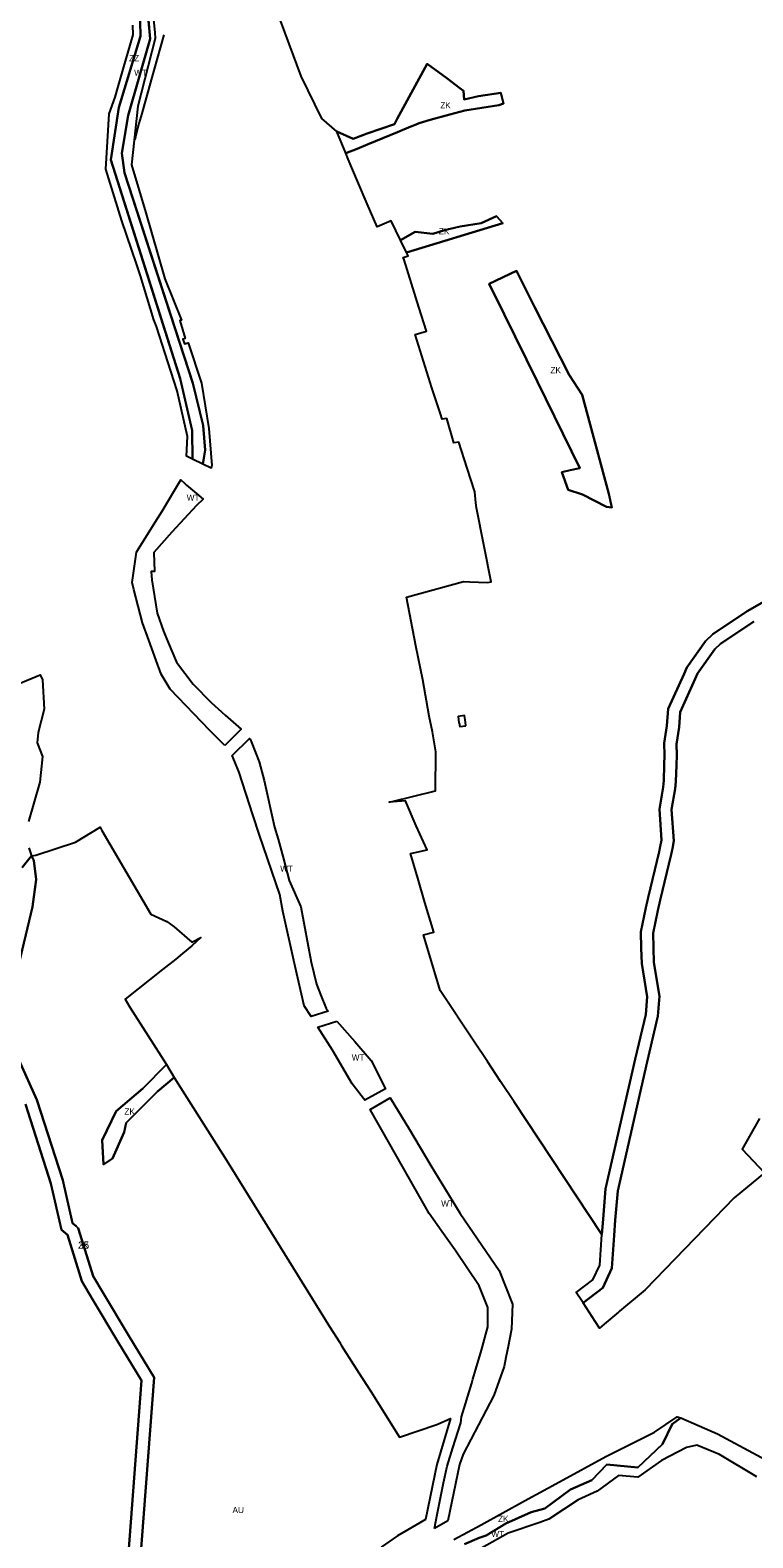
# Model space of a CAD drawing. Extents: x -521261 to -517465, y -1182764 to -1179456.
# Drawn here: x -519568 to -518978, y -1182068 to -1180835 of the extents above; entities that cross this region are included whole.
import ezdxf

# ---------------------------------------------------------------- set-up
doc = ezdxf.new("R2010")
doc.units = 0
for name, color, linetype in [('90640013', 7, 'Continuous'), ('90670013', 7, 'Continuous'), ('90710013', 7, 'Continuous'), ('90710023', 7, 'Continuous'), ('90750013', 7, 'Continuous'), ('90910012', 7, 'Continuous'), ('ID_navrh', 7, 'Continuous')]:
    doc.layers.add(name, color=color, linetype=linetype)

msp = doc.modelspace()

# ---------------------------------------------------------------- linework, layer by layer
at = {"layer": '90640013'}
for points in [[(-519473.15, -1180811.61), (-519470.44, -1180842.25), (-519488.4, -1180904.99), (-519493.48, -1180935.68), (-519491.42, -1180951.86), (-519435.57, -1181123.54), (-519427.15, -1181158.29), (-519425.48, -1181178.36), (-519427.239, -1181189.828), (-519435.742, -1181185.683), (-519435.91, -1181162.44), (-519445.77, -1181119.72), (-519502.58, -1180941.01), (-519495.82, -1180898.23), (-519478.12, -1180840), (-519478.91, -1180815.91)], [(-519213.54, -1182072.66), (-519201.77, -1182067.5), (-519195.94, -1182065.5), (-519179.95, -1182055.88), (-519159.13, -1182046.65), (-519148.1, -1182043.62), (-519126.93, -1182028.03), (-519109.68, -1182020.3), (-519097.34, -1182007.47), (-519072.08, -1182009.92), (-519051.9, -1181990.97), (-519043.95, -1181974.52), (-519037.03, -1181969.53), (-519007.07, -1181982.5), (-518967.52, -1182003.69)], [(-518974.73, -1182017.76), (-519005.47, -1181999.42), (-519023.89, -1181991.86), (-519032.35, -1181993.68), (-519052.86, -1182004.21), (-519071.99, -1182018.05), (-519087.95, -1182016.65), (-519105.37, -1182029.49), (-519120.85, -1182036.4), (-519144.87, -1182052.15), (-519152.16, -1182054.92), (-519178.02, -1182063.84), (-519208.47, -1182080.89)]]:
    msp.add_lwpolyline(points, dxfattribs=at)
for points in [[(-519409.389, -1181419.917), (-519412.61, -1181416.64), (-519421.56, -1181407.62), (-519454.05, -1181373.8), (-519461.32, -1181361.65), (-519465.42, -1181350.42), (-519471.53, -1181333.7), (-519476.71, -1181319.53), (-519483.7, -1181292.46), (-519485.03, -1181286.53), (-519481.6, -1181261.79), (-519479.97, -1181259.11), (-519464.29, -1181234.25), (-519460.68, -1181228.41), (-519450.28, -1181210.83), (-519445.38, -1181202.73), (-519442.35, -1181205.48), (-519440.69, -1181206.91), (-519432.6, -1181213.97), (-519427.07, -1181218.6), (-519432.4, -1181223.78), (-519452.53, -1181245.44), (-519467.41, -1181262.05), (-519466.74, -1181277.55), (-519469.58, -1181277.72), (-519469.05, -1181284.33), (-519464.71, -1181311.78), (-519459.51, -1181326.26), (-519455.66, -1181335.73), (-519448.71, -1181351.86), (-519435.17, -1181369.79), (-519420.51, -1181384.61), (-519409.19, -1181394.99), (-519395.935, -1181406.485)], [(-519324.89, -1181637.01), (-519324.89, -1181637.01), (-519338.936, -1181641.334), (-519344.46, -1181632.66), (-519351.95, -1181600.47), (-519362.01, -1181555.36), (-519364.56, -1181541.56), (-519380.95, -1181493.03), (-519386.52, -1181476.56), (-519397.54, -1181441.8), (-519401.11, -1181433.16), (-519403.401, -1181428.069), (-519389.322, -1181414.013), (-519388.77, -1181414.67), (-519387.43, -1181418.03), (-519381.19, -1181433.32), (-519377.23, -1181448.55), (-519368.74, -1181486.67), (-519365.68, -1181496.5), (-519361.63, -1181511.27), (-519356.79, -1181530.1), (-519347.34, -1181551.68), (-519338.86, -1181596.87), (-519334.56, -1181614.89), (-519331.36, -1181623.53), (-519326.59, -1181634.95)], [(-519317.776, -1181645.284), (-519303.16, -1181661.78), (-519289.97, -1181677.24), (-519278.04, -1181700.51), (-519295.09, -1181709.75), (-519296.21, -1181708.36), (-519298.01, -1181706.05), (-519305.33, -1181696.42), (-519321.38, -1181668.9), (-519333.365, -1181650.082)], [(-519238.255, -1182059.95), (-519235.92, -1182048.33), (-519230.66, -1182022.59), (-519227.85, -1182009.01), (-519223.16, -1181994.1), (-519216.64, -1181973.55), (-519215.94, -1181968.54), (-519207.75, -1181941.19), (-519206.76, -1181937.89), (-519205.11, -1181932.39), (-519199.86, -1181914.01), (-519194.44, -1181895.04), (-519194.53, -1181879.24), (-519201.77, -1181861.67), (-519221.32, -1181832.36), (-519230.68, -1181818.97), (-519242.36, -1181802.29), (-519281.3, -1181733.63), (-519286.8, -1181724.28), (-519290.763, -1181717.333), (-519274.23, -1181707.9), (-519258.46, -1181733.82), (-519241.25, -1181763.27), (-519217.16, -1181802.34), (-519185.2, -1181849.05), (-519174.51, -1181876.42), (-519175.37, -1181897.02), (-519178.25, -1181912.58), (-519178.69, -1181914.95), (-519179.74, -1181920.09), (-519181.25, -1181927.45), (-519189.77, -1181951.14), (-519214.66, -1181999.21), (-519217.66, -1182007.47), (-519227.185, -1182053.534)]]:
    msp.add_lwpolyline(points, close=True, dxfattribs=at)
at = {"layer": '90670013'}
for points in [[(-519469.058, -1180813.289), (-519466.67, -1180837.06), (-519466.18, -1180841.84), (-519480.35, -1180897.31), (-519485.52, -1180945.19), (-519473.83, -1180984.46), (-519464.097, -1181018.489), (-519458.43, -1181038.3), (-519444.83, -1181072.14), (-519445.99, -1181072.34), (-519441.75, -1181087.15), (-519443.6, -1181087.68), (-519442.29, -1181091.61), (-519439.26, -1181090.75), (-519428.49, -1181123.78), (-519422.52, -1181160.74), (-519419.92, -1181190.94), (-519420.397, -1181193.163), (-519427.239, -1181189.828), (-519425.48, -1181178.36), (-519427.15, -1181158.29), (-519435.57, -1181123.54), (-519469.036, -1181020.668), (-519491.42, -1180951.86), (-519493.48, -1180935.68), (-519488.4, -1180904.99), (-519470.44, -1180842.25), (-519473.044, -1180812.806)], [(-519478.91, -1180815.91), (-519478.12, -1180840), (-519495.82, -1180898.23), (-519502.58, -1180941.01), (-519476.374, -1181023.446), (-519445.77, -1181119.72), (-519435.91, -1181162.44), (-519435.742, -1181185.683), (-519440.793, -1181183.221), (-519439.93, -1181167.27), (-519448.2, -1181129.83), (-519458.37, -1181098.48), (-519460.28, -1181092.58), (-519465.27, -1181077.26), (-519466.73, -1181073.28), (-519467.25, -1181071.87), (-519478.17, -1181035.82), (-519481.61, -1181026.09), (-519493.55, -1180991.1), (-519506.51, -1180948.83), (-519503.72, -1180903.54), (-519498.93, -1180889.82), (-519492.45, -1180866.93), (-519484.35, -1180839.02), (-519484.62, -1180831.05)]]:
    msp.add_lwpolyline(points, dxfattribs=at)
at = {"layer": '90710013'}
for points in [[(-519268.52, -1180907.46), (-519253.98, -1180880.7), (-519244.16, -1180862.53), (-519228.167, -1180874.44), (-519217.362, -1180882.487), (-519214.35, -1180884.73), (-519213.96, -1180891.71), (-519202.16, -1180889.15), (-519184.03, -1180886.23), (-519181.69, -1180894.95), (-519185.49, -1180896.3), (-519213.45, -1180900.71), (-519225.65, -1180904.08), (-519241.56, -1180908.49), (-519250.72, -1180911.24), (-519254.39, -1180912.8), (-519257.44, -1180913.87), (-519268.27, -1180918.36), (-519292.23, -1180928.39), (-519301.18, -1180932.18), (-519310.648, -1180935.544), (-519317.97, -1180917.99), (-519304.48, -1180923.88), (-519293.06, -1180919.67), (-519270.91, -1180912.06)], [(-519239.59, -1181001.51), (-519230.03, -1180998.72), (-519217.21, -1180995.57), (-519199.91, -1180992.98), (-519187.6, -1180987.07), (-519182.22, -1180992.98), (-519261.07, -1181016.81), (-519265.89, -1181006.88), (-519253.85, -1181000.02)], [(-519095.79, -1181214.24), (-519093.4, -1181225.17), (-519097.52, -1181224.74), (-519117.3, -1181214.66), (-519128.84, -1181210.98), (-519134.006, -1181196.371), (-519127.28, -1181194.73), (-519119.41, -1181193.2), (-519154.06, -1181122.61), (-519181.18, -1181067.29), (-519193.42, -1181042.39), (-519171.09, -1181031.72), (-519156.38, -1181061.23), (-519128.11, -1181116.88), (-519117.61, -1181133.12), (-519111.04, -1181157.52)], [(-519491.57, -1181735.94), (-519501.06, -1181757.42), (-519508.54, -1181762.3), (-519509.68, -1181742.43), (-519498.2, -1181718.82), (-519476.47, -1181700.33), (-519457.1, -1181680.7), (-519450.65, -1181691.27), (-519464.34, -1181702.69), (-519489.97, -1181728.17)]]:
    msp.add_lwpolyline(points, close=True, dxfattribs=at)
msp.add_lwpolyline([(-519222.3, -1182068.89), (-519199.92, -1182056.85), (-519164.56, -1182037.39), (-519135.97, -1182021.78), (-519098.32, -1182001.18), (-519058.43, -1181981.09), (-519040, -1181968.57), (-519037.03, -1181969.53), (-519043.95, -1181974.52), (-519051.9, -1181990.97), (-519072.08, -1182009.92), (-519097.34, -1182007.47), (-519109.68, -1182020.3), (-519126.93, -1182028.03), (-519148.1, -1182043.62), (-519159.13, -1182046.65), (-519179.95, -1182055.88), (-519195.94, -1182065.5), (-519201.77, -1182067.5), (-519213.54, -1182072.66)], dxfattribs=at)
at = {"layer": '90710023'}
for points in [[(-518977.383, -1181318.492), (-519004.519, -1181336.714), (-519009.203, -1181341.219), (-519023.249, -1181361.087), (-519025.201, -1181365.417), (-519037.519, -1181392.468), (-519038.432, -1181404.848), (-519040.407, -1181418.631), (-519040.238, -1181427.77), (-519040.424, -1181436.046), (-519040.96, -1181449.219), (-519041.573, -1181455.371), (-519044.435, -1181472.293), (-519042.763, -1181497.712), (-519043.876, -1181504.139), (-519044.799, -1181508.83), (-519053.852, -1181546.315), (-519055.755, -1181554.74), (-519059.551, -1181573.17), (-519059.214, -1181585.154), (-519058.91, -1181597.25), (-519054.496, -1181624.81), (-519055.598, -1181641.135), (-519064.409, -1181678.49), (-519088.456, -1181783.836), (-519090.501, -1181807.769), (-519091.421, -1181820.385), (-519093.367, -1181847.085), (-519100.708, -1181863.197), (-519116.836, -1181875.406), (-519117.928, -1181873.724), (-519122.3, -1181867), (-519108.76, -1181856.75), (-519103.21, -1181844.57), (-519101.394, -1181819.658), (-519100.47, -1181806.98), (-519098.36, -1181782.29), (-519074.15, -1181676.23), (-519065.52, -1181639.64), (-519064.55, -1181625.27), (-519068.89, -1181598.17), (-519069.21, -1181585.42), (-519069.58, -1181572.29), (-519065.53, -1181552.63), (-519063.59, -1181544.04), (-519054.57, -1181506.69), (-519053.71, -1181502.32), (-519052.82, -1181497.18), (-519054.49, -1181471.78), (-519051.49, -1181454.04), (-519050.94, -1181448.52), (-519050.42, -1181435.73), (-519050.24, -1181427.75), (-519050.42, -1181418.01), (-519048.38, -1181403.77), (-519047.36, -1181389.95), (-519034.31, -1181361.29), (-519031.97, -1181356.1), (-519016.82, -1181334.67), (-519010.82, -1181328.9), (-518982.66, -1181309.99), (-518953.51, -1181293.31)], [(-519574.763, -1181519.484), (-519567.26, -1181509.91), (-519565.36, -1181513.85), (-519563.51, -1181529.49), (-519566.46, -1181551.62), (-519579.08, -1181604.33)], [(-519577.34, -1181677.47), (-519562.88, -1181709.42), (-519541.79, -1181775.11), (-519533.67, -1181810.31), (-519530.74, -1181812.82), (-519529.03, -1181814.46), (-519523.41, -1181832.63), (-519516.92, -1181853.55), (-519508.53, -1181867.8), (-519487.9, -1181902.3), (-519467.21, -1181936.45), (-519478.73, -1182090.66)], [(-519489.037, -1182094.401), (-519477.42, -1181938.895), (-519496.468, -1181907.457), (-519517.13, -1181872.903), (-519526.127, -1181857.622), (-519532.962, -1181835.589), (-519537.803, -1181819.937), (-519542.674, -1181815.764), (-519551.44, -1181777.767), (-519572.226, -1181713.022)]]:
    msp.add_lwpolyline(points, dxfattribs=at)
at = {"layer": '90750013'}
for points in [[(-518953.51, -1181293.31), (-518982.66, -1181309.99), (-519010.82, -1181328.9), (-519016.82, -1181334.67), (-519031.97, -1181356.1), (-519034.31, -1181361.29), (-519047.36, -1181389.95), (-519048.38, -1181403.77), (-519050.42, -1181418.01), (-519050.24, -1181427.75), (-519050.42, -1181435.73), (-519050.94, -1181448.52), (-519051.49, -1181454.04), (-519054.49, -1181471.78), (-519052.82, -1181497.18), (-519053.71, -1181502.32), (-519054.57, -1181506.69), (-519063.59, -1181544.04), (-519065.53, -1181552.63), (-519069.58, -1181572.29), (-519069.21, -1181585.42), (-519068.89, -1181598.17), (-519064.55, -1181625.27), (-519065.52, -1181639.64), (-519074.15, -1181676.23), (-519098.36, -1181782.29), (-519100.47, -1181806.98), (-519101.394, -1181819.658), (-519173.08, -1181711.239), (-519184.157, -1181694.485), (-519194.956, -1181678.152), (-519205.871, -1181661.644), (-519233.36, -1181620.07), (-519247.21, -1181574.73), (-519238.79, -1181572.54), (-519246.09, -1181548.32), (-519251.7, -1181528.29), (-519257.65, -1181508.26), (-519244.05, -1181505.15), (-519252.99, -1181485.52), (-519261.93, -1181465.17), (-519275.14, -1181466.21), (-519272.69, -1181465.63), (-519237.38, -1181456.93), (-519236.95, -1181424.9), (-519239.68, -1181408.57), (-519242.41, -1181395.97), (-519247.74, -1181366.2), (-519253.5, -1181338.25), (-519260.93, -1181298.71), (-519214.55, -1181285.79), (-519209.28, -1181285.94), (-519195.05, -1181286.72), (-519191.78, -1181286.11), (-519203.84, -1181225.47), (-519204.3, -1181221.58), (-519205.22, -1181212.45), (-519211.39, -1181193.2), (-519218.22, -1181171.9), (-519222.4, -1181172.34), (-519228.13, -1181152.65), (-519231.918, -1181153.175), (-519233.32, -1181148.86), (-519236.78, -1181138.21), (-519240.2, -1181127.43), (-519253.993, -1181083.953), (-519244.79, -1181081.1), (-519251.03, -1181061.46), (-519256.86, -1181042.2), (-519262.94, -1181022.92), (-519263.605, -1181020.81), (-519259.672, -1181019.689), (-519261.07, -1181016.81), (-519182.22, -1180992.98), (-519187.6, -1180987.07), (-519199.91, -1180992.98), (-519217.21, -1180995.57), (-519230.03, -1180998.72), (-519239.59, -1181001.51), (-519253.85, -1181000.02), (-519265.89, -1181006.88), (-519273.45, -1180991.01), (-519284.93, -1180995.85), (-519293.04, -1180977.04), (-519300.92, -1180958.54), (-519308.56, -1180940.55), (-519310.648, -1180935.544), (-519301.18, -1180932.18), (-519292.23, -1180928.39), (-519268.27, -1180918.36), (-519257.44, -1180913.87), (-519254.39, -1180912.8), (-519250.72, -1180911.24), (-519241.56, -1180908.49), (-519225.65, -1180904.08), (-519213.45, -1180900.71), (-519185.49, -1180896.3), (-519181.69, -1180894.95), (-519184.03, -1180886.23), (-519202.16, -1180889.15), (-519213.96, -1180891.71), (-519214.35, -1180884.73), (-519217.362, -1180882.487), (-519228.167, -1180874.44), (-519244.16, -1180862.53), (-519253.98, -1180880.7), (-519268.52, -1180907.46), (-519270.91, -1180912.06), (-519293.06, -1180919.67), (-519304.48, -1180923.88), (-519317.97, -1180917.99), (-519330.01, -1180907.41), (-519346.93, -1180872.84), (-519370.039, -1180810.159)], [(-518972.73, -1181724.81), (-518986.79, -1181749.85), (-518968.7, -1181769.11), (-518993.46, -1181789.66), (-519066.19, -1181864.73), (-519087.04, -1181882.36), (-519087.74, -1181882.98), (-519099.42, -1181892.97), (-519103.33, -1181896.18), (-519106.847, -1181890.769), (-519116.836, -1181875.406), (-519100.708, -1181863.197), (-519093.367, -1181847.085), (-519091.421, -1181820.385), (-519090.501, -1181807.769), (-519088.456, -1181783.836), (-519064.409, -1181678.49), (-519055.598, -1181641.135), (-519054.496, -1181624.81), (-519058.91, -1181597.25), (-519059.214, -1181585.154), (-519059.551, -1181573.17), (-519055.755, -1181554.74), (-519053.852, -1181546.315), (-519044.799, -1181508.83), (-519043.876, -1181504.139), (-519042.763, -1181497.712), (-519044.435, -1181472.293), (-519041.573, -1181455.371), (-519040.96, -1181449.219), (-519040.424, -1181436.046), (-519040.238, -1181427.77), (-519040.407, -1181418.631), (-519038.432, -1181404.848), (-519037.519, -1181392.468), (-519025.201, -1181365.417), (-519023.249, -1181361.087), (-519009.203, -1181341.219), (-519004.519, -1181336.714), (-518977.383, -1181318.492)], [(-519577.82, -1181369.5), (-519560.15, -1181361.95), (-519558.28, -1181366.15), (-519556.82, -1181390.16), (-519561.9, -1181409.19), (-519562.53, -1181417.65), (-519558.29, -1181428.74), (-519560.34, -1181449.96), (-519569.85, -1181481.93)], [(-519579.08, -1181604.33), (-519566.46, -1181551.62), (-519563.51, -1181529.49), (-519565.36, -1181513.85), (-519567.26, -1181509.91), (-519563.86, -1181509.62), (-519531.34, -1181498.84), (-519511.19, -1181486.58), (-519509.72, -1181489.33), (-519469.92, -1181557.79), (-519456.65, -1181563.71), (-519450.63, -1181567.98), (-519436.26, -1181580.5), (-519428.99, -1181576.87), (-519436.43, -1181583.74), (-519444.05, -1181589.92), (-519449.37, -1181594.38), (-519460.32, -1181602.95), (-519490.67, -1181627.18), (-519486.95, -1181633.64), (-519457.1, -1181680.7), (-519476.47, -1181700.33), (-519498.2, -1181718.82), (-519509.68, -1181742.43), (-519508.54, -1181762.3), (-519501.06, -1181757.42), (-519491.57, -1181735.94), (-519489.97, -1181728.17), (-519464.34, -1181702.69), (-519450.65, -1181691.27), (-519407.91, -1181758.76), (-519323.87, -1181894.73), (-519315.5, -1181907.95), (-519314.23, -1181910.15), (-519299.96, -1181932.54), (-519293.32, -1181942.71), (-519289.74, -1181948.32), (-519287.24, -1181952.67), (-519273.97, -1181973.58), (-519266.78, -1181985.29), (-519236.18, -1181974.91), (-519225.183, -1181970.09), (-519236.113, -1182007.614), (-519245.606, -1182052.653), (-519250.079, -1182055.246), (-519259.955, -1182060.97), (-519268.355, -1182065.839), (-519281.77, -1182075.133)], [(-519569.38, -1181503.52), (-519567.26, -1181509.91), (-519574.763, -1181519.484)], [(-519478.73, -1182090.66), (-519467.21, -1181936.45), (-519487.9, -1181902.3), (-519508.53, -1181867.8), (-519516.92, -1181853.55), (-519523.41, -1181832.63), (-519529.03, -1181814.46), (-519530.74, -1181812.82), (-519533.67, -1181810.31), (-519541.79, -1181775.11), (-519562.88, -1181709.42), (-519577.34, -1181677.47)], [(-519572.226, -1181713.022), (-519551.44, -1181777.767), (-519542.674, -1181815.764), (-519537.803, -1181819.937), (-519532.962, -1181835.589), (-519526.127, -1181857.622), (-519517.13, -1181872.903), (-519496.468, -1181907.457), (-519477.42, -1181938.895), (-519489.037, -1182094.401), (-519490.964, -1182123.644), (-519496.983, -1182156.235), (-519510.122, -1182231.787), (-519530.261, -1182347.588), (-519534.18, -1182347.06), (-519550.42, -1182341.81), (-519569.087, -1182337.379)]]:
    msp.add_lwpolyline(points, dxfattribs=at)
for points in [[(-519093.4, -1181225.17), (-519095.79, -1181214.24), (-519111.04, -1181157.52), (-519117.61, -1181133.12), (-519128.11, -1181116.88), (-519156.38, -1181061.23), (-519171.09, -1181031.72), (-519193.42, -1181042.39), (-519181.18, -1181067.29), (-519154.06, -1181122.61), (-519119.41, -1181193.2), (-519127.28, -1181194.73), (-519134.006, -1181196.371), (-519128.84, -1181210.98), (-519117.3, -1181214.66), (-519097.52, -1181224.74)], [(-519212.46, -1181403.8), (-519212.84, -1181400.66), (-519213.49, -1181395.41), (-519218.86, -1181396.18), (-519218.13, -1181401.43), (-519217.94, -1181401.4), (-519217.55, -1181404.42)]]:
    msp.add_lwpolyline(points, close=True, dxfattribs=at)
at = {"layer": '90910012'}
for points in [[(-519462.25, -1180849.48), (-519469.64, -1180875.84)], [(-519459.09, -1180839.02), (-519462.25, -1180849.48)], [(-519469.64, -1180875.84), (-519477.11, -1180903.14)], [(-519479.5, -1180911.27), (-519481.85, -1180919.92)], [(-519477.11, -1180903.14), (-519479.5, -1180911.27)], [(-519481.85, -1180919.92), (-519482.84, -1180924.79)], [(-519482.84, -1180924.79), (-519483.313, -1180924.749)]]:
    msp.add_lwpolyline(points, dxfattribs=at)

# ---------------------------------------------------------------- texts
at = {"layer": '90640013'}
for rotation, p in [(0, (-519483.392, -1180872.42)), (0, (-519440.483, -1181219.784)), (0, (-519364.146, -1181522.95)), (360, (-519305.702, -1181677.346)), (360, (-519232.637, -1181796.708)), (0, (-519191.667, -1182066.864))]:
    msp.add_text('WT', height=5, rotation=rotation, dxfattribs=at).set_placement(p)
at = {"layer": '90670013'}
msp.add_text('ZZ', height=5, rotation=0, dxfattribs=at).set_placement((-519487.541, -1180860.504))
at = {"layer": '90710013'}
for p in [(-519233.393, -1180899.037), (-519234.544, -1181001.94), (-519143.41, -1181115.534), (-519491.382, -1181721.5), (-519186.213, -1182054.485)]:
    msp.add_text('ZK', height=5, rotation=360, dxfattribs=at).set_placement(p)
at = {"layer": '90710023'}
msp.add_text('ZK', height=5, rotation=360, dxfattribs=at).set_placement((-519529.095, -1181831.226))
at = {"layer": '90750013'}
msp.add_text('AU', height=5, rotation=360, dxfattribs=at).set_placement((-519403.081, -1182047.296))
at = {"layer": 'ID_navrh'}
msp.add_text('35', height=6, rotation=360, dxfattribs=at).set_placement((-519529.095, -1181831.226))

doc.saveas('drawing.dxf')
